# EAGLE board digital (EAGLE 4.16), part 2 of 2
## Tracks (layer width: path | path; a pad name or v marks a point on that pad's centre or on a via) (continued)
N$360  (via drill 0.9, 3.2)  (5 unrouted) (continued)
  Top 0.406: IC2.34 47.14,41.85 47.14,41.9 | IC2.26 47.14,47.05 47.14,46.98 | 47.14,46.35 47.14,46.98 | IC2.27 47.14,46.4 47.14,46.35 | 47.14,45.71 47.14,45.75 IC2.28 45.69,45.84 45.72,45.87 43.65,45.87 43.33,45.55 C9.2 | IC2.30 47.14,44.45 47.14,44.44 | 47.14,37.95 47.78,37.95 | 47.78,37.95 48.41,37.95 | 48.41,37.95 49.84,37.95 | 49.84,37.95 50.48,37.95 | 50.48,37.95 50.95,37.95 | 50.95,37.95 54.92,37.95 | 54.92,37.95 58.89,37.95 | 58.89,37.95 59.37,37.95 59.53,38.09 | 59.53,38.09 | 59.53,38.09 59.53,38.73 | IC2.41 47.14,36.48 47.14,37.95 | IC2.42 47.78,36.48 47.78,37.95 | 48.41,37.95 48.41,36.51 48.41,36.48 | 49.84,37.95 49.84,37.94 49.76,37.85 IC2.45 49.81,36.48 49.84,36.51 49.84,35.08 44.29,29.52 43.02,29.52 | 50.48,37.95 50.48,37.94 50.41,37.87 IC2.46 | 50.95,37.95 50.95,37.94 51.06,37.83 IC2.47 | 54.92,37.95 54.92,37.94 54.96,37.9 IC2.53 | 58.89,37.95 58.89,37.94 58.86,37.9 IC2.59 | IC2.15 50.41,50.23 50.48,50.16 | C7.2 12.06,33.17 12.85,32.38 IC1.6 v22.54,32.38 | 23.34,32.22 IC1.18 23.34,24.12 23.49,23.96 | 23.34,32.22 23.34,32.37 23.33,32.38 28.25,32.38 IC1.28 31.11,32.38 32.06,31.43 33.17,31.43 33.33,31.58 C6.2 | 23.34,32.22 23.33,32.22 23.17,32.38 v22.54,32.38 | v22.54,32.38 | v22.54,32.38 IC1.39 22.54,43.97 23.97,45.4 23.99,45.69 C4.2 | 59.53,41.9 59.58,41.85 IC2.67 62.91,41.85 63.05,41.72 | IC2.66 59.59,41.2 59.53,41.27 | IC2.72 59.71,45.1 59.53,45.08 | IC2.70 59.53,43.8 59.53,43.81 | 63.05,41.72 63.18,41.59 | 63.05,41.72 C18.1 | R18.2 41.59,28.1 43.02,29.52 | 43.02,29.52 41.59,28.09 41.59,22.85 46.98,22.85 47.14,22.7 47.15,22.7 | R17.2 47.15,22.86 47.14,22.85 52.7,22.85 | 52.86,22.85 52.71,22.85 52.7,22.85
  Top 0.406: C27.2 52.73,22.88 52.7,22.85 | 52.7,22.85 58.26,22.85 63.65,22.85 63.69,22.89 64.13,23.33 C47.- | 49.84,50.16 47.3,50.16 47.14,50 47.14,46.98 | R8.1 52.07,56.5 52.38,56.19 52.38,55.4 | 23.49,23.96 24.52,22.93 | 24.52,22.93 24.68,22.77 24.36,22.77 I2C.4 | I2C.4 | 24.52,22.93 | 24.52,22.93 24.92,22.54 24.92,19.28 23.49,19.28 23.49,21.42 | 23.49,23.96 23.49,21.42 | C39.1 24.25,20.66 23.49,21.42 | 46.19,31.43 45.72,30.95 40.32,30.95 40.32,12.06 40.32,11.9 | 53.02,50.48 53.02,52.22 52.38,52.86 | 52.38,52.86 52.38,55.4 | 52.38,55.4 52.38,57.22 44.45,57.22 44.45,55.08 46.11,55.08 46.83,55.79 46.83,55.8 46.91,55.87 51.91,55.87 52.38,55.4
  Top 0.61: 50.72,2.06 51.83,2.06 51.83,0.55 38.97,0.55 38.97,4.99 | 1.11,42.86 1.11,39.68 1.9,39.68 | 4.2,39.68 4.44,39.68 4.76,39.36 RST.1 | 4.2,39.68 1.9,39.68 | 33.81,31.58 | C6.2 33.81,31.58 | C3.1 35.39,33.17 33.81,31.58 | 37.46,45.4 LCD.1 | C36.1 51.43,1.42 50.8,2.06 IC3.5 50.8,4.36 50.08,3.64 48.26,3.64 | 57.22,8.8 55.72,7.3 49.68,7.3 49.37,7.61 | SMA2.3 48.22,8.76 49.37,7.61 | 1.27,42.86 0.71,42.94 1.03,46.67 1.34,46.82 C37.1 | LCD.1 | 36.35,43.02 36.51,43.17 LCD.1 | 4.2,39.68 5,39.68 5.23,39.44 5.23,36.43 6.11,35.55 | 1.9,39.68 1.03,40.55 | 43.18,8.73 38.97,8.73 | 38.97,4.99 38.97,4.76 40,3.72 40.4,3.72 40.79,3.33 R24.2 | 38.97,7.61 38.97,4.99 | 38.97,8.73 38.97,7.61 | 38.97,8.73 38.97,10.71 40.32,12.06 | 49.37,7.61 49.37,8.8 48.41,9.76 43.33,9.76 41.83,11.27 | 40.08,8.57 39.92,8.57 38.97,7.61
  Top 0.813: 19.52,10.15 18.89,10.79 18.89,14.28 18.91,14.25 C38.2 | 47.14,42.22 45.4,42.22 | 36.19,39.92 36.19,37.94 35.24,36.98
  Top 1.016: R9.1 46.19,55.71 46.98,56.51 47.78,56.51 R7.1 | C13.2 52.07,28.96 52.7,28.33 R16.2 | R16.2 | R16.2
  Top 1.27: C7.2 11.16,33.04 9.76,34.44 9.6,34.6 8.96,35.24 5.87,35.24 5.63,35 | 5.63,35 5.23,34.6 5.23,33.17 4.92,32.85 1.42,32.85 1.42,31.27 1.42,29.36 C2.1 | 5.63,35 | RST.1 4.76,35.87 5.63,35 | C4.2 25.52,45.53 26.19,46.19 34.92,46.19 | 34.92,46.19 37.46,46.19 37.46,45.4 37.46,44.28 | LCD.1 37.46,44.28 | 37.46,44.28 | 43.81,34.44 | 43.81,34.44 C12.2 | 43.84,36.69 43.84,34.47 43.81,34.44 | 35.4,37.14 | 35.4,37.14 C23.- | C3.1 35.39,37.14 35.4,37.14 | 34.92,46.19 LCD.3 | 34.92,46.19 | SMA1.3 62.38,8.81 62.38,8.8 63.5,9.92 63.5,11.42
  Top 1.422: ISP.6 | ISP.4 ISP.6 | ISP.6 | ISP.8 | ISP.6 ISP.8 | ISP.8 | ISP.10 | ISP.8 ISP.10 | ISP.10 | R22.1 | 41.59,14.76 R22.1 | 41.59,20 41.59,14.76 | 41.59,25.55 41.59,20 | 41.59,25.55 R18.2 41.59,27.77 40.95,28.41 C22.- | 41.59,14.76 C35.2 | 41.59,20 41.62,20.02 C34.2 | 41.59,25.55 | 41.59,25.55 C33.2 | R21.1 | R21.1 | 47.15,14.76 R21.1 | 47.15,20.15 47.15,14.76 | 47.15,20.15 47.15,22.7 47.15,25.71 | 47.15,25.71 R17.2 | 47.15,14.76 47.14,14.76 | 47.14,14.76 C32.2 | 47.14,14.76 | 47.15,20.15 47.14,20.15 | 47.15,20.15 C31.2 | 47.15,25.71 47.14,25.71 47.17,25.68 C30.2 | R16.2 52.71,25.39 | 52.71,14.76 R20.1 | 52.71,20.15 52.71,14.76 | 52.71,20.15 52.71,22.85 52.71,25.39 | 52.71,25.39 52.7,25.39 52.73,25.42 C27.2 | 52.71,20.15 52.7,20.15 | 52.7,20.15 C28.2 | 52.7,20.15 | 52.71,14.76 52.7,14.76 | 52.7,14.76 C29.2 | 52.7,14.76 | R19.1 58.26,14.76 | 58.26,20 58.26,14.76 | 58.26,20 58.26,22.85 58.26,25.55 | 58.26,25.55 R15.2 | 58.26,14.76 | 58.26,14.76 C26.2 | 58.26,14.76 | 58.26,20 58.29,20.02 C25.2 | 58.26,25.55 | 58.26,25.55 C24.2 | X2.7 | X2.7 74.45,45.24 73.34,46.34 R14.1 71.75,46.51 71.75,48.09 R6.1 76.51,43.33 76.51,41.82 | X2.7 74.45,41.74 73.34,40.63 72.07,40.63 C20.1 | R11.1 62.54,30.8 63.5,29.84 63.5,23.33 C47.- | R22.1 | R22.1 40.3,11.41 C45.- 41.91,10 SMA2.2 | C14.- 64.45,52.38 63.18,51.11 63.18,48.73 C17.1 | C21.- 75.88,23.33 76.51,22.85 76.51,23.17 | 76.51,23.17 76.51,41.82 | 76.51,11.98 76.51,11.42 76.5,11.42 66.52,11.42 66.03,11.9 65.88,11.9 C46.- 63.75,11.44 63.5,11.42 63.5,13.57 | 76.51,13.17 76.51,11.98 | 76.51,13.17 76.51,19.6 | 76.51,19.6 76.51,23.17 | R8.1 | R8.1 47.78,56.51 | R8.1 | SMA2.2 43.18,8.73 48.18,8.73 48.26,8.8 | SMA2.2 | ISP.6 7.85,44.13 7.68,44.3 C5.- | 63.69,22.89 63.5,22.85 63.5,13.57
  Top 1.422: 57.23,8.81 SMA1.2 | SMA1.3 57.23,8.81 | 57.23,8.81 57.22,8.8 | 57.3,3.72 57.32,3.71 SMA1.4 62.35,3.68 62.54,3.49 R23.2 | 76.51,11.98 76.51,0.95 58.97,0.95 58.97,2.06 57.3,3.72 | SMA2.4 | SMA2.4 SMA2.5 42.58,3.68 42.3,3.41 40.87,3.41 R24.2 | SMA2.4 48.26,3.64 | 57.3,3.72 57.29,3.71 SMA1.5 | 64.45,12.22 64.29,12.22 | 64.45,12.22 75.56,12.22 76.51,13.17 | 63.5,13.57 63.5,13.17 64.45,12.22 | 76.51,41.82 76.51,52.14 73.58,52.14 73.58,50 72.7,49.13 74.45,48.49 74.29,48.33 | 76.51,19.6 76.51,19.92 75,21.42 75,27.38
  Bottom 0.254: v35.87,33.73 42.7,33.73 v45.56,36.74
N$361
  Top 0.254: 5.23,43.65 4.84,43.65
N$362
  Top 0.406: 16.98,37.14 16.98,36.66
N$363
  Top 1.016: 16.19,37.7 16.19,36.98
N$364
  Top 0.406: 14.68,33.25 13.33,34.6
N$365
  Top 0.305: 14.6,33.25 16.35,33.25
N$366
  Top 0.305: 16.19,33.09 13.65,33.09 13.49,33.25
N$367
  Top 0.61: 13.65,33.73 | 14.04,33.33 13.65,33.73
N$368
  Top 0.305: 12.54,35.39 12.54,36.51 10.39,36.51 10.16,36.27 10.16,35.71 10.71,35.16 12.7,35.16
N$369
  Top 0.406: 12.93,32.38 10.71,32.38 10.71,33.01
N$370
  Top 0.254: 12.54,32.62 12.54,33.81 10.87,33.81
N$371
  Top 0.406: 10.08,31.58 8.33,33.33 8.33,33.81 6.74,33.81 6.74,32.3
N$372
  Top 0.406: 8.41,31.19 8.41,28.81 2.85,28.81 2.85,31.35 5.63,31.35 6.82,32.54
N$373
  Top 0.406: 9.44,31.82 9.44,31.74 8.17,30.47
N$374
  Top 0.813: 6.82,31.98 6.19,31.35
N$375
  Top 0.813: 8.81,31.43 8.73,31.43 8.57,31.27
N$376
  Top 0.813: 9.2,31.98 8.41,31.98
N$377
  Top 0.813: 8.65,32.54 8.65,32.38
N$378
  Top 1.422: 73.81,15.47 73.81,14.6 65.8,14.6 65.8,18.41 65.8,19.12 66.59,19.12
N$379
  Top 1.422: 69.45,15.63 68.34,15.63 67.3,16.66 67.3,15.47 67.23,15.39
N$380
  Top 0.305: 65.08,22.22 66.11,22.22 66.11,20.95 65.48,20.95 63.97,19.44
N$381
  Top 0.813: 65.08,21.03 65,21.03 64.13,20.15 64.13,20.79 64.21,20.87
N$382
  Top 0.305: 22.62,38.89 22.62,44.44
N$383
  Top 0.305: 26.59,46.03 26.59,45.87 25.39,44.68 23.09,44.68
N$384
  Top 0.305: 25.39,45.24 25.39,44.84
N$385
  Top 0.813: 25.63,46.43 24.2,46.43
N$386
  Top 0.813: 23.81,45.63 23.73,45.63 22.86,44.76
N$387
  Top 0.406: 23.33,41.03 23.33,43.09 23.57,43.33 25.24,43.33 25.24,41.74 24.05,41.74 23.33,41.03 | 23.33,41.03 23.33,38.97
N$388
  Top 0.406: 23.97,42.14 23.97,42.06 23.49,41.59
N$389
  Top 0.406: 38.17,46.27 38.17,43.81 37.94,43.57
N$390
  Top 0.305: 37.06,43.41 34.68,43.41 34.21,43.89 34.21,44.68 32.94,45.95
N$391
  Top 0.61: 35.71,43.25 35.87,43.25 36.19,42.94
N$392
  Top 0.61: 33.65,45.71 33.73,45.71 34.44,45
N$394
  Top 0.406: 28.65,36.98 28.65,36.66 28.57,36.59
N$395
  Top 0.406: 28.49,38.41 26.74,38.41
N$396
  Top 0.406: 27.93,37.86 26.66,37.86
N$397
  Top 0.61: 19.2,51.11 17.93,49.84 17.93,50.95 18.57,50.95 | 18.57,50.95 18.73,50.95 | 18.17,50.56 18.57,50.95
N$398
  Top 0.305: 31.74,40.4 31.74,41.9 32.06,42.22 32.62,42.22 33.02,41.82 33.02,41.35 28.81,37.14
N$399
  Top 0.305: 31.98,40.79 31.98,41.67
N$400
  Top 0.305: 32.22,41.35 32.22,41.11 32.14,41.03
N$401
  Top 0.305: 32.06,42.06 32.62,42.06
N$402
  Top 0.813: 27.3,41.9 26.59,41.19
N$403
  Top 0.813: 27.46,41.59 27.46,41.43
N$404
  Top 0.406: 34.84,40.55 35.48,41.19 35.48,41.9 35.16,42.22 34.68,42.22 34.36,41.9 34.36,40.16
N$405
  Top 0.406: 34.68,40.63 34.68,41.98
N$406
  Top 0.61: 35.08,41.9 35.08,41.19
N$407
  Top 0.406: 36.9,41.67 36.9,41.74 | 36.9,41.67 36.9,41.11 37.94,40.08 | 36.9,41.67 36.9,41.82 37.22,42.14 37.78,42.14 39.05,40.87 39.05,40.16 40.4,38.81 | 40.4,38.81 | 40.4,38.81 40.48,38.73 40.48,36.35 39.76,36.35 38.73,35.32
N$408
  Top 1.016: 39.13,39.52 39.13,38.01 39.21,37.94
N$409
  Top 1.016: 39.84,38.01 39.84,38.89
N$410
  Top 1.016: 39.29,36.9 39.29,36.43
N$411
  Top 0.406: 20.95,47.14 20.95,48.73 21.35,49.13 22.54,49.13 22.54,47.78 22.14,47.78 20.95,46.59
N$412
  Top 0.406: 21.74,47.78 21.74,47.7 21.11,47.06
N$413
  Top 0.61: 17.62,47.54 15.71,47.54 15.71,45.4 16.43,44.68
N$414
  Top 0.406: 26.66,49.92 30.16,49.92
N$415
  Top 0.406: 32.14,48.02 32.14,49.76 36.59,49.76 36.9,49.44 36.9,48.25 36.67,48.02 32.14,48.02
N$416
  Top 0.406: 17.54,38.73 18.57,38.73
N$417
  Top 0.61: 16.74,45.48 16.74,45
N$418
  Top 0.305: 15.95,44.92 15.95,39.76 18.17,37.54 18.57,37.54
N$419
  Top 0.406: 18.09,37.78 18.09,38.57
N$420
  Top 0.406: 52.7,29.12 52.7,29.04 53.34,28.41 53.34,22.93
N$421
  Top 0.406: 52.78,28.81 52.78,30.39 51.35,30.39 51.35,29.04 52.07,28.33 52.07,22.93
N$422
  Top 0.406: 47.78,28.33 47.78,23.09 47.7,23.01
N$423
  Top 0.406: 46.51,23.01 46.51,28.41 47.78,28.41 47.7,28.33
N$425
  Top 0.61: 56.27,8.8 56.27,7.77 57.15,7.77 57.62,8.25 57.07,8.25 56.99,8.17
N$426
  Top 0.61: 56.27,8.88 57.07,9.68
N$427
  Top 0.406: 55.72,33.81 56.03,33.49 56.03,31.27 56.91,30.39
N$428
  Top 0.406: 55.56,35.39 55.08,34.92
N$429
  Top 0.406: 55.08,34.92 55.08,31.43 55.95,30.55
N$430
  Top 0.406: 55.4,33.25 55.4,34.84
N$431
  Top 0.406: 55.8,33.41 55.8,33.25
N$432
  Top 0.406: 55.88,31.82 55.88,31.19 56.51,30.55
N$433
  Top 0.406: 55.32,31.82 55.32,31.51 55.4,31.43
N$434
  Top 0.406: 57.7,33.17 57.94,33.17 57.94,31.66 56.99,31.66 56.99,33.73
N$435
  Top 0.406: 57.15,33.33 57.15,33.17
N$436
  Top 0.406: 59.61,32.54 60.32,32.54 60.32,31.03 58.97,31.03 58.97,33.25
N$437
  Top 0.406: 59.21,32.78 59.21,32.54
N$438
  Top 0.305: 61.11,34.28 61.11,33.73 61.59,33.25
N$439
  Top 0.305: 60.64,33.81 60.64,33.65
N$440
  Top 0.406: 65.16,33.73 65.16,33.65 64.53,33.01
N$441
  Top 0.813: 64.61,32.85 64.61,31.51
N$442
  Top 0.406: 63.73,33.17 63.81,33.17 64.37,32.62
N$443
  Top 0.406: 58.65,33.57 58.65,35 57.3,35
N$444
  Top 0.813: 58.02,34.76 58.41,34.36
N$445
  Top 0.406: 32.38,23.17 32.38,21.66 32.22,21.5
N$446
  Top 0.406: 32.3,23.17 31.11,23.17 31.11,21.66 31.27,21.5
N$447
  Top 0.61: 31.59,19.44 31.51,19.44 30.4,18.33
N$448
  Top 0.254: 37.86,32.38 35.71,32.38 35.71,31.11
N$449
  Top 0.254: 35.55,30.63 37.94,30.63
N$450
  Top 0.254: 37.86,30.87 37.3,30.87
N$451
  Top 0.406: 38.1,33.01 37.94,33.01 37.22,32.3
N$452
  Top 0.406: 37.06,31.03 37.06,30.87 38.02,29.92
N$453
  Top 1.422: 13.57,46.9 13.57,50.79
PA0
  Top 0.406: IC1.37 24.14,40.49 24.6,40.95 25.79,40.95 | LCD.10 27.3,41.43 26.82,40.95 26.74,40.95 | 25.79,40.95 26.74,40.95 | 26.74,40.95 27.46,40.95 27.86,41.35 27.86,41.98 27.62,42.22 27.06,42.22 25.79,40.95
PA1
  Top 0.305: LCD.9 | LCD.9 27.93,43.49 28.57,42.86 28.57,40.79 28.49,40.71
  Top 0.406: IC1.36 24.94,40.02 25.08,40.16 27.93,40.16 28.49,40.71 | LCD.9 | 27.93,43.49 27.93,44.36 27.54,44.76 27.06,44.76 26.66,44.36 26.66,43.89 27.06,43.49 27.93,43.49
PA2
  Top 0.406: IC1.35 25.74,39.23 25.87,39.36 26.03,39.52 28.57,39.52 29.76,40.71 | 29.76,40.71 29.84,40.79 29.84,41.43 LCD.8 | 29.76,40.71 30.4,41.35 30.4,41.98 30.16,42.22 29.6,42.22 29.28,41.9 29.28,40.32
  Top 0.813: 29.84,41.74 29.84,41.43 29.84,41.35 29.52,41.03
PA3
  Top 0.305: LCD.7 30.47,43.49 31.11,42.86 31.11,40.79 31.03,40.71
  Top 0.406: IC1.34 28.5,38.18 28.57,38.25 | 28.57,38.25 29.05,38.73 | 28.57,38.25 27.93,37.62 26.51,37.62 | 29.05,38.73 26.51,38.73 | 29.05,38.73 31.03,40.71 | 29.68,43.49 30.47,43.49 29.6,43.49 29.28,43.81 | 29.28,43.81 | 29.28,43.81 29.2,43.89 29.2,44.36 29.6,44.76 30.08,44.76 30.47,44.36 30.47,43.57 | LCD.7
PA4  (1 unrouted)
  Top 0.406: LCD.6 32.38,40.95 28.89,37.46 | 28.89,37.46 28.34,36.91 | 28.89,37.46 28.89,36.35 | 27.86,36.43 28.89,37.46
PA5
  Top 0.305: 33.57,40.71 33.65,40.79 33.65,42.86 33.02,43.49 LCD.5
  Top 0.406: IC1.32 29.55,35.58 29.84,35.87 29.84,36.98 | 29.84,36.98 | 29.84,36.98 33.57,40.71 | LCD.5 | 33.02,43.49 33.02,44.36 32.62,44.76 32.06,44.76 31.74,44.44 31.74,43.89 32.14,43.49 33.02,43.49
PA6
  Top 0.406: IC1.31 30.02,34.78 30.71,35.47 30.71,36.51 34.92,40.63 34.92,41.27 | 34.92,41.27 | 34.92,41.27 LCD.4
(copper drawn outside any net)
  shapes: Top area x55, Top circle x2

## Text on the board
Top: 2008 Michal Slomkowski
